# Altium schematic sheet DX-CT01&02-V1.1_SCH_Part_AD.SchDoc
size A4; SheetNumber: 1; SheetTotal: 1
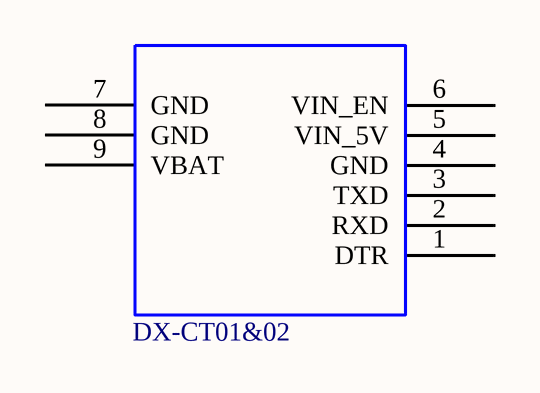
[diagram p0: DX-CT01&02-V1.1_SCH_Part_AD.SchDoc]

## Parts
DX-CT01&02  *  (value not drawn)

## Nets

Not connected (* = marked no-connect by the designer): DX-CT01&02 1(DTR) 2(RXD) 3(TXD) 4(GND) 5(VIN_5V) 6(VIN_EN) 7(GND) 8(GND) 9(VBAT)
